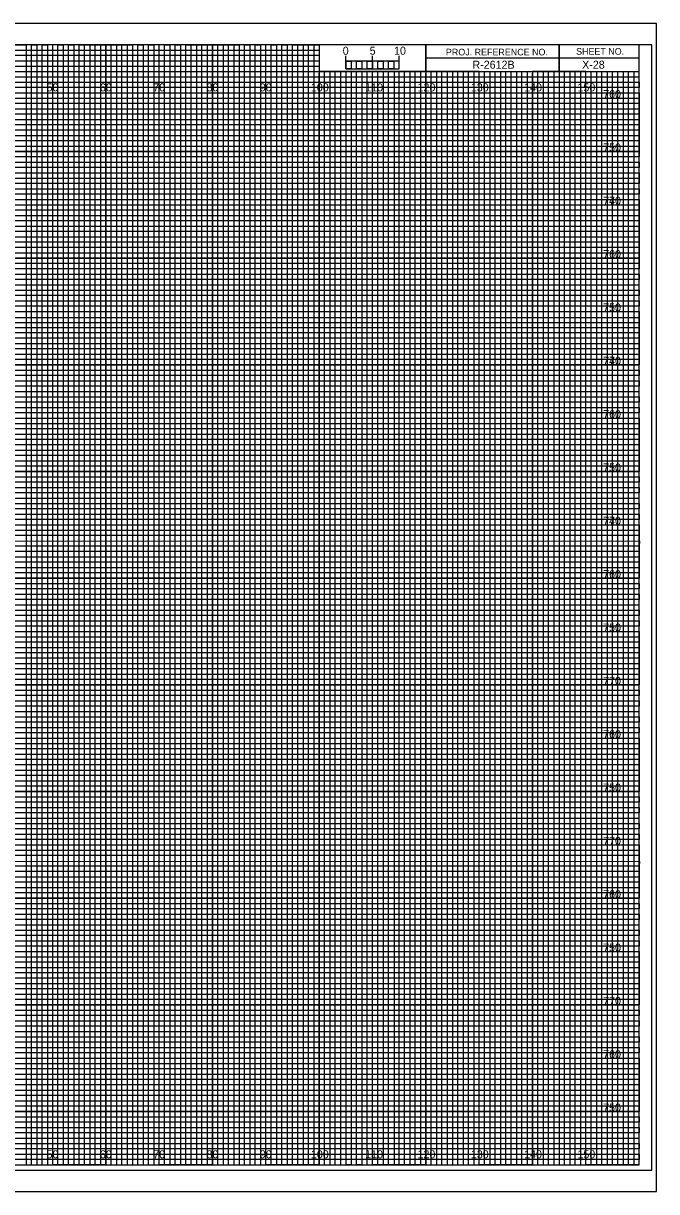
# Model space of a CAD drawing. Extents: x -13 to 323, y 2195 to 2414.
# Drawn here: x 204.5 to 323.3, y 2195 to 2414 of the extents above; entities that cross this region are included whole.
import ezdxf

# ---------------------------------------------------------------- set-up
doc = ezdxf.new("R2010")
doc.units = 0
for name, color, linetype in [('Exist Cross Section Cell', 7, 'Continuous'), ('Exist XS Center Line Elevation Label', 7, 'Continuous'), ('Exist XS Ground Line', 7, 'Continuous'), ('Prop XS Ditch Slope Text', 7, 'Continuous'), ('Prop XS Ditch Standard Text', 7, 'Continuous'), ('Prop XS Dump Level', 7, 'Continuous'), ('Prop XS EOT Tick Mark', 7, 'Continuous'), ('Prop XS Finish Grade', 7, 'Continuous'), ('Prop XS Finish Grade Earthwork', 7, 'Continuous'), ('Prop XS Finish Grade Paved Shoulder', 7, 'Continuous'), ('Prop XS Finish Grade Pavement', 7, 'Continuous'), ('Prop XS Hydro Fill Slope Data', 7, 'Continuous'), ('Prop XS Hydro Typical Ditch Data', 7, 'Continuous'), ('Prop XS SS Elevation Text', 7, 'Continuous'), ('Prop XS Subgrade Earthwork', 7, 'Continuous')]:
    doc.layers.add(name, color=color, linetype=linetype)

msp = doc.modelspace()

# ---------------------------------------------------------------- linework, layer by layer
at = {"layer": 'Exist XS Center Line Elevation Label'}
for points in [[(195, 2410), (205, 2410), (205, 2200), (215, 2200), (215, 2410), (225, 2410), (225, 2200), (235, 2200), (235, 2410), (245, 2410), (245, 2200), (255, 2200), (255, 2410), (259.93, 2410), (260, 2410), (260, 2405), (264.99, 2405), (264.99, 2200), (275, 2200), (275, 2405), (285, 2405), (285, 2200), (295, 2200), (295, 2405), (305, 2405), (305, 2200), (315, 2200), (315, 2405)], [(0, 2405), (275, 2405)], [(0, 2385), (320, 2385), (320, 2395), (0, 2395)], [(0, 2365), (320, 2365), (320, 2375), (0, 2375)], [(0, 2345), (320, 2345), (320, 2355), (0, 2355)], [(0, 2325), (320, 2325), (320, 2335), (0, 2335)], [(0, 2305), (320, 2305), (320, 2315), (0, 2315)], [(0, 2285), (320, 2285), (320, 2295), (0, 2295)], [(0, 2265), (320, 2265), (320, 2275), (0, 2275)], [(0, 2245), (320, 2245), (320, 2255), (0, 2255)], [(0, 2225), (320, 2225), (320, 2235), (0, 2235)], [(0, 2205), (320, 2205), (320, 2215), (0, 2215)]]:
    msp.add_lwpolyline(points, dxfattribs=at)
at = {"layer": 'Exist XS Ground Line'}
for p, q in [((210, 2410), (200, 2410)), ((210, 2200), (210, 2410)), ((230, 2410), (220, 2410)), ((220, 2410), (220, 2200)), ((230, 2200), (230, 2410)), ((250, 2410), (240, 2410)), ((240, 2410), (240, 2200)), ((250, 2200), (250, 2410)), ((260, 2410), (260, 2200)), ((270, 2200), (270, 2405)), ((290, 2405), (280, 2405)), ((280, 2405), (280, 2200)), ((290, 2200), (290, 2405)), ((310, 2405), (300, 2405)), ((300, 2405), (300, 2200)), ((310, 2200), (310, 2405)), ((220, 2200), (210, 2200)), ((240, 2200), (230, 2200)), ((260, 2200), (250, 2200)), ((280, 2200), (270, 2200)), ((300, 2200), (290, 2200)), ((320, 2200), (310, 2200)), ((320, 2200), (320, 2200))]:
    msp.add_line(p, q, dxfattribs=at)
for points in [[(0, 2400), (320, 2400), (320, 2390), (0, 2390)], [(0, 2380), (320, 2380), (320, 2370), (0, 2370)], [(0, 2360), (320, 2360), (320, 2350), (0, 2350)], [(0, 2340), (320, 2340), (320, 2330), (0, 2330)], [(0, 2320), (320, 2320), (320, 2310), (0, 2310)], [(0, 2300), (320, 2300), (320, 2290), (0, 2290)], [(0, 2280), (320, 2280), (320, 2270), (0, 2270)], [(0, 2260), (320, 2260), (320, 2250), (0, 2250)], [(0, 2240), (320, 2240), (320, 2230), (0, 2230)], [(0, 2220), (320, 2220), (320, 2210), (0, 2210)]]:
    msp.add_lwpolyline(points, dxfattribs=at)
at = {"layer": 'Prop XS Ditch Slope Text'}
for p, q in [((267, 2405), (266.01, 2405)), ((266.01, 2405), (266.01, 2200)), ((267, 2200), (267, 2405)), ((269, 2405), (268, 2405)), ((268, 2405), (268, 2200)), ((269, 2200), (269, 2405)), ((266.01, 2200), (265, 2200)), ((268, 2200), (267, 2200))]:
    msp.add_line(p, q, dxfattribs=at)
for points in [[(205, 2200), (206, 2200), (206, 2410), (207, 2410), (207, 2200)], [(207, 2200), (208, 2200), (208, 2410), (209, 2410), (209, 2200)], [(210, 2200), (211, 2200), (211, 2410), (212, 2410), (212, 2200)], [(212, 2200), (213, 2200), (213, 2410), (214, 2410), (214, 2200)], [(215, 2200), (216, 2200), (216, 2410), (217, 2410), (217, 2200)], [(217, 2200), (218, 2200), (218, 2410), (219, 2410), (219, 2200)], [(220, 2200), (221, 2200), (221, 2410), (222, 2410), (222, 2200)], [(222, 2200), (223, 2200), (223, 2410), (224, 2410), (224, 2200)], [(225, 2200), (226, 2200), (226, 2410), (227, 2410), (227, 2200)], [(227, 2200), (228, 2200), (228, 2410), (229, 2410), (229, 2200)], [(230, 2200), (231, 2200), (231, 2410), (232, 2410), (232, 2200)], [(232, 2200), (233, 2200), (233, 2410), (234, 2410), (234, 2200)], [(235, 2200), (236, 2200), (236, 2410), (237, 2410), (237, 2200)], [(237, 2200), (238, 2200), (238, 2410), (239, 2410), (239, 2200)], [(240, 2200), (241, 2200), (241, 2410), (242, 2410), (242, 2200)], [(242, 2200), (243, 2200), (243, 2410), (244, 2410), (244, 2200)], [(245, 2200), (246, 2200), (246, 2410), (247, 2410), (247, 2200)], [(247, 2200), (248, 2200), (248, 2410), (249, 2410), (249, 2200)], [(250, 2200), (251, 2200), (251, 2410), (252, 2410), (252, 2200)], [(252, 2200), (253, 2200), (253, 2410), (254, 2410), (254, 2200)], [(255, 2200), (256, 2200), (256, 2410), (257, 2410), (257, 2200)], [(257, 2200), (258, 2200), (258, 2410), (259, 2410), (259, 2200)], [(260, 2200), (261, 2200), (261, 2405), (262.02, 2405), (262.02, 2200)], [(262, 2200), (263, 2200), (263, 2405), (263.99, 2405), (263.99, 2200)], [(270, 2200), (270.98, 2200), (270.98, 2405), (272, 2405), (272, 2200)], [(272, 2200), (273, 2200), (273, 2405), (274.05, 2405), (274.05, 2200)], [(275, 2200), (276, 2200), (276, 2405), (277, 2405), (277, 2200)], [(277, 2200), (278, 2200), (278, 2405), (279, 2405), (279, 2200)], [(280, 2200), (281, 2200), (281, 2405), (282, 2405), (282, 2200)], [(282, 2200), (283, 2200), (283, 2405), (284, 2405), (284, 2200)], [(285, 2200), (286, 2200), (286, 2405), (287, 2405), (287, 2200)], [(287, 2200), (288, 2200), (288, 2405), (289, 2405), (289, 2200)], [(290, 2200), (291, 2200), (291, 2405), (292, 2405), (292, 2200)], [(292, 2200), (293, 2200), (293, 2405), (294, 2405), (294, 2200)], [(295, 2200), (296, 2200), (296, 2405), (297, 2405), (297, 2200)], [(297, 2200), (298, 2200), (298, 2405), (299, 2405), (299, 2200)], [(300, 2200), (301, 2200), (301, 2405), (302, 2405), (302, 2200)], [(302, 2200), (303, 2200), (303, 2405), (304, 2405), (304, 2200)], [(305, 2200), (306, 2200), (306, 2405), (307, 2405), (307, 2200)], [(307, 2200), (308, 2200), (308, 2405), (309, 2405), (309, 2200)], [(310, 2200), (311, 2200), (311, 2405), (312, 2405), (312, 2200)], [(312, 2200), (313, 2200), (313, 2405), (314, 2405), (314, 2200)], [(315, 2200), (316, 2200), (316, 2405), (317, 2405), (317, 2200)], [(317, 2200), (318, 2200), (318, 2405), (319, 2405), (319, 2200)]]:
    msp.add_lwpolyline(points, dxfattribs=at)
at = {"layer": 'Prop XS Ditch Standard Text'}
for p, q in [((305, 2410), (305, 2405)), ((305, 2405), (305, 2410)), ((280, 2407.5), (280, 2405)), ((320, 2407.49), (280, 2407.49)), ((280, 2405), (320, 2405))]:
    msp.add_line(p, q, dxfattribs=at)
for points in [[(320, 2410), (0, 2410), (0, 2200), (320, 2200)], [(280, 2410), (260, 2410), (260, 2405.03), (280, 2405.03)], [(320, 2410), (280, 2410), (280, 2405), (320, 2405)]]:
    msp.add_lwpolyline(points, close=True, dxfattribs=at)
at = {"layer": 'Prop XS Dump Level'}
for p, q in [((0, 2409), (260, 2409)), ((260, 2409), (260, 2407.98)), ((260, 2407.98), (0, 2407.98)), ((0, 2407), (260, 2407)), ((260, 2407), (260, 2405.89)), ((260, 2405.89), (0, 2405.89)), ((0, 2404), (320, 2404))]:
    msp.add_line(p, q, dxfattribs=at)
for points in [[(0, 2403), (270, 2403), (320, 2403), (320, 2402), (0, 2402)], [(0, 2401), (320, 2401), (320, 2399), (0, 2399)], [(0, 2398), (320, 2398), (320, 2397), (0, 2396.98)], [(0, 2396), (320, 2396), (320, 2394), (0, 2394)], [(0, 2393), (320, 2393), (320, 2392), (0, 2392)], [(0, 2391), (320, 2391), (320, 2389), (0, 2389)], [(0, 2388), (320, 2388), (320, 2387), (0, 2387)], [(0, 2386), (320, 2386), (320, 2384), (0, 2384)], [(0, 2383), (320, 2383), (320, 2382), (0, 2382)], [(0, 2381), (320, 2381), (320, 2379), (0, 2379)], [(0, 2378), (320, 2378), (320, 2377), (0, 2377)], [(0, 2376), (320, 2376), (320, 2373.95), (320, 2373), (320, 2372), (0, 2372)], [(0, 2374), (320, 2374), (320, 2373), (0, 2373)], [(0, 2371), (320, 2371), (320, 2369), (0, 2369.03)], [(0, 2369.03), (320, 2369), (320, 2368), (0, 2368)], [(0, 2367), (320, 2367), (320, 2366), (0, 2366)], [(0, 2364), (320, 2364), (320, 2363), (0, 2363)], [(0, 2362), (320, 2362), (320, 2361), (0, 2361)], [(-0.07, 2358.89), (320, 2358.89), (320, 2357.88), (-0.07, 2357.88)], [(0, 2357), (320, 2357), (320, 2356), (0, 2356)], [(0, 2354), (320, 2354), (320, 2353), (0, 2353)], [(0, 2352), (320, 2352), (320, 2351), (0, 2351)], [(0, 2349), (320, 2349), (320, 2348), (0, 2348)], [(0, 2347), (320, 2347), (320, 2346), (0, 2346)], [(0, 2344), (320, 2344), (320, 2343), (0, 2343)], [(0, 2342), (320, 2342), (320, 2341), (0, 2341)], [(0, 2339), (320, 2339), (319.99, 2337.98), (0, 2338)], [(0, 2337), (320, 2337), (320, 2336), (0, 2336)], [(0, 2334), (320, 2334), (320, 2333), (0, 2333)], [(0, 2332), (320, 2332), (320, 2331), (0, 2331)], [(0, 2329), (320, 2329), (320, 2328), (0, 2328)], [(0, 2327), (320, 2327), (320, 2326), (0, 2326)], [(0, 2324), (320, 2324), (320, 2323), (0, 2323)], [(0, 2322), (320, 2322), (320, 2321), (0, 2321)], [(0, 2319), (320, 2319), (320, 2318), (0, 2318)], [(0, 2316.99), (320.07, 2316.91), (320, 2316), (0, 2316)], [(0, 2314), (320, 2314), (320, 2313), (0, 2313)], [(0, 2312), (320, 2312), (320, 2311), (0, 2311)], [(0, 2309), (320, 2309), (320, 2308), (0, 2308)], [(0, 2307), (320, 2307), (320, 2306), (0, 2306)], [(0, 2304), (320, 2304), (320, 2303), (0, 2303)], [(0, 2302), (320, 2302), (320, 2301), (0, 2301)], [(0, 2299), (320, 2299), (320, 2298), (0, 2298)], [(0, 2297), (320, 2297), (320, 2296), (0, 2296)], [(0, 2294), (320, 2294), (320, 2293), (0, 2293)], [(0, 2292), (320, 2292), (320, 2291), (0, 2291)], [(0, 2289), (320, 2289), (320, 2288), (0, 2288)], [(0, 2287), (320, 2287), (320, 2286), (0, 2286)], [(0, 2284), (320, 2284), (320, 2283), (0, 2283)], [(0, 2282), (320, 2282), (320, 2281), (0, 2281)], [(0, 2279), (320, 2279), (319.99, 2277.98), (0, 2278)], [(0, 2277), (320, 2277), (320, 2276), (0, 2276)], [(0, 2274), (320, 2274), (320, 2273), (0, 2273)], [(0, 2272), (320, 2272), (320, 2271), (0, 2271)], [(0, 2269), (320, 2269), (320, 2268), (0, 2268)], [(0, 2267), (320, 2267), (320, 2266), (0, 2266)], [(0, 2264), (320, 2264), (320, 2263), (0, 2263)], [(0, 2262), (320, 2262), (320, 2261), (0, 2261)], [(0, 2259), (320, 2259), (320, 2258), (0, 2258)], [(0, 2256.99), (320.07, 2256.91), (320, 2256), (0, 2256)], [(0, 2254), (320, 2254), (320, 2253), (0, 2253)], [(0, 2252), (320, 2252), (320, 2251), (0, 2251)], [(0, 2249), (320, 2249), (320, 2248), (0, 2248)], [(0, 2247), (320, 2247), (320, 2246), (0, 2246)], [(0, 2244), (320, 2244), (320, 2243), (0, 2243)], [(0, 2242), (320, 2242), (320, 2241), (0, 2241)], [(0, 2239), (320, 2239), (320, 2238), (0, 2238)], [(0, 2237), (320, 2237), (320, 2236), (0, 2236)], [(0, 2234), (320, 2234), (320, 2233), (0, 2233)], [(0, 2232), (320, 2232), (320, 2231), (0, 2231)], [(0, 2229), (320, 2229), (320, 2228), (0, 2228)], [(0, 2227), (320, 2227), (320, 2226), (0, 2226)], [(0, 2224), (320, 2224), (320, 2223), (0, 2223)], [(0, 2222), (320, 2222), (320, 2221), (0, 2221)], [(0, 2219), (320, 2219), (320, 2218), (0, 2218)], [(0, 2217), (320, 2217), (320, 2216), (0, 2216)], [(0, 2214), (320, 2214), (320, 2213), (0, 2213)], [(0, 2212), (320, 2212), (320, 2211), (0, 2211)], [(0, 2209), (320, 2209), (320, 2208), (0, 2208)], [(0, 2207), (320, 2207), (320, 2206), (0, 2206)], [(0, 2204), (320, 2204), (320, 2203), (0, 2203)], [(0, 2202), (320, 2202), (320, 2201), (0, 2201)]]:
    msp.add_lwpolyline(points, dxfattribs=at)
at = {"layer": 'Prop XS Finish Grade'}
for p, q in [((210, 2200), (210, 2410)), ((220, 2200), (220, 2410)), ((230, 2200), (230, 2410)), ((240, 2200), (240, 2410)), ((250, 2200), (250, 2410)), ((260, 2200), (260, 2404.69)), ((270, 2200), (270, 2404.69)), ((280, 2200), (280, 2404.69)), ((290, 2200), (290, 2404.69)), ((300, 2200), (300, 2404.69)), ((310, 2200), (310, 2404.69)), ((0, 2400), (320, 2400)), ((0, 2390), (320, 2390)), ((0, 2380), (320, 2380)), ((0, 2370), (320, 2370)), ((0, 2360), (320, 2360)), ((0, 2350), (320, 2350)), ((0, 2340), (320, 2340)), ((0, 2330), (320, 2330)), ((0, 2320), (320, 2320)), ((0, 2310), (320, 2310)), ((0, 2300), (320, 2300)), ((0, 2290), (320, 2290)), ((0, 2280), (320, 2280)), ((0, 2270), (320, 2270)), ((0, 2260), (320, 2260)), ((0, 2250), (320, 2250)), ((0, 2240), (320, 2240)), ((0, 2230), (320, 2230)), ((0, 2220), (320, 2220)), ((0, 2210), (320, 2210))]:
    msp.add_line(p, q, dxfattribs=at)
at = {"layer": 'Prop XS Finish Grade Earthwork'}
msp.add_lwpolyline([(-10.8, 2199), (322.4, 2199), (322.4, 2410), (-10.8, 2410)], close=True, dxfattribs=at)
at = {"layer": 'Prop XS Hydro Typical Ditch Data'}
msp.add_lwpolyline([(-13.4, 2195), (323.3, 2195), (323.3, 2414), (-13.4, 2414)], close=True, dxfattribs=at)
at = {"layer": 'Prop XS SS Elevation Text'}
for p, q in [((265, 2405.49), (265, 2407.9)), ((265, 2406.9), (265, 2407.9)), ((270, 2405.49), (270, 2407.9)), ((275, 2405.49), (275, 2407.9)), ((275, 2406.9), (275, 2407.9))]:
    msp.add_line(p, q, dxfattribs=at)
for points in [[(275, 2406.9), (265, 2406.9), (265, 2405.49), (275, 2405.49)], [(265, 2406.9), (266, 2406.9), (266, 2405.49), (265, 2405.49)], [(267, 2406.9), (268, 2406.9), (268, 2405.49), (267, 2405.49)], [(269, 2406.9), (270, 2406.9), (270, 2405.49), (269, 2405.49)], [(271, 2406.9), (272, 2406.9), (272, 2405.49), (271, 2405.49)], [(273, 2406.9), (274, 2406.9), (274, 2405.49), (273, 2405.49)]]:
    msp.add_lwpolyline(points, close=True, dxfattribs=at)
at = {"layer": 'Prop XS Subgrade Earthwork'}
for p, q in [((323.3, 2414), (-13.4, 2414)), ((-13.4, 2195), (323.3, 2195))]:
    msp.add_line(p, q, dxfattribs=at)

# ---------------------------------------------------------------- texts
at = {"layer": 'Exist Cross Section Cell'}
for s, p in [('50', (208.86, 2401.25)), ('60', (218.86, 2401.25)), ('70', (228.86, 2401.25)), ('80', (238.86, 2401.25)), ('90', (248.86, 2401.25)), ('100', (258.44, 2401.25)), ('110', (268.62, 2401.25)), ('120', (278.44, 2401.25)), ('130', (288.44, 2401.25)), ('140', (298.44, 2401.25)), ('150', (308.44, 2401.25)), ('50', (208.86, 2201.25)), ('60', (218.86, 2201.25)), ('70', (228.86, 2201.25)), ('80', (238.86, 2201.25)), ('90', (248.86, 2201.25)), ('100', (258.44, 2201.25)), ('110', (268.62, 2201.25)), ('120', (278.44, 2201.25)), ('130', (288.44, 2201.25)), ('140', (298.44, 2201.25)), ('150', (308.44, 2201.25))]:
    msp.add_text(s, height=1.5, dxfattribs=at).set_placement(p)
at = {"layer": 'Prop XS Ditch Standard Text'}
for s, p in [('PROJ. REFERENCE NO.', (283.77, 2407.99)), ('SHEET NO.', (308.19, 2408.12))]:
    msp.add_text(s, height=1.25, dxfattribs=at).set_placement(p)
at = {"layer": 'Prop XS EOT Tick Mark'}
msp.add_text('X-28', height=1.5, dxfattribs=at).set_placement((309.32, 2405.5))
at = {"layer": 'Prop XS Finish Grade Paved Shoulder'}
for s, p in [('760', (313.26, 2400)), ('750', (313.26, 2390)), ('770', (313.26, 2380)), ('740', (313.26, 2380)), ('760', (313.26, 2370)), ('750', (313.26, 2360)), ('770', (313.26, 2350)), ('740', (313.26, 2350)), ('760', (313.26, 2340)), ('750', (313.26, 2330)), ('770', (313.26, 2320)), ('740', (313.26, 2320)), ('760', (313.26, 2310)), ('750', (313.26, 2300)), ('770', (313.26, 2290)), ('760', (313.26, 2280)), ('750', (313.26, 2270)), ('770', (313.26, 2260)), ('760', (313.26, 2250)), ('750', (313.26, 2240)), ('770', (313.26, 2230)), ('760', (313.26, 2220)), ('750', (313.26, 2210))]:
    msp.add_text(s, height=1.5, dxfattribs=at).set_placement(p)
at = {"layer": 'Prop XS Finish Grade Pavement'}
msp.add_text('R-2612B', height=1.5, dxfattribs=at).set_placement((288.74, 2405.5))
at = {"layer": 'Prop XS Hydro Fill Slope Data'}
for s, p in [('5', (269.47, 2408.12)), ('10', (274.04, 2408.12))]:
    msp.add_text(s, height=1.5, dxfattribs=at).set_placement(p)
at = {"layer": 'Prop XS SS Elevation Text'}
msp.add_text('0', height=1.5, dxfattribs=at).set_placement((264.41, 2408.12))

doc.saveas('drawing.dxf')
